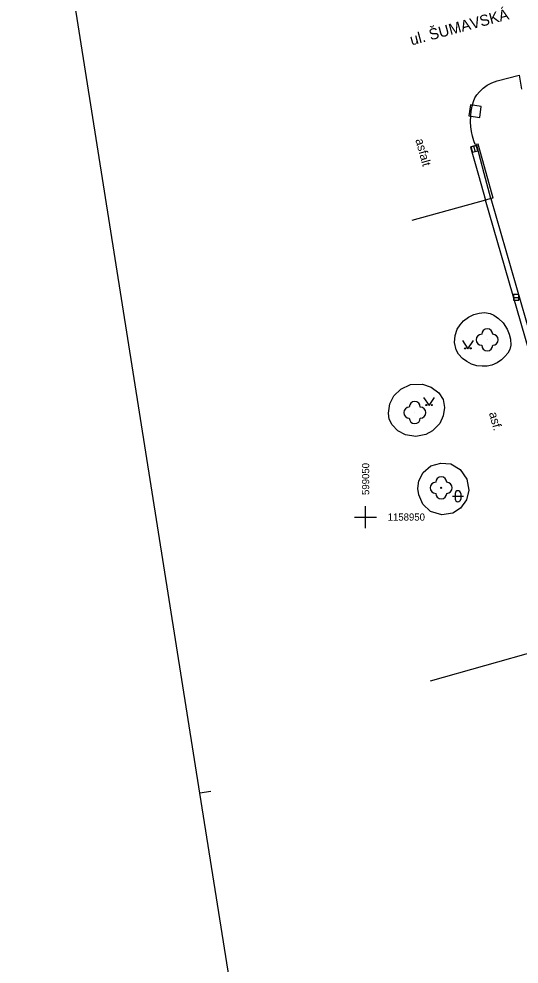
# Model space of a CAD drawing. Extents: x -599098 to -598820, y -1159597 to -1158744.
# Drawn here: x -599081.5 to -599036.1, y -1158990.5 to -1158904.8 of the extents above; entities that cross this region are included whole.
import ezdxf

# ---------------------------------------------------------------- set-up
doc = ezdxf.new("R2010")
doc.units = 0
for name, color, linetype in [('budovy', 7, 'Continuous'), ('druh pozemku stromy', 7, 'Continuous'), ('hektometrická síť', 7, 'Continuous'), ('kresba', 7, 'Continuous'), ('mapový rám legenda', 7, 'Continuous'), ('popisy', 7, 'Continuous'), ('značky IS', 7, 'Continuous')]:
    doc.layers.add(name, color=color, linetype=linetype)

msp = doc.modelspace()

# ---------------------------------------------------------------- linework, layer by layer
at = {"layer": 'budovy'}
msp.add_lwpolyline([(-599044.099, -1158964.859), (-599029.33, -1158960.69)], dxfattribs=at)
at = {"layer": 'druh pozemku stromy'}
for p, q in [((-599042.126, -1158948.116), (-599041.126, -1158948.116)), ((-599041.876, -1158947.866), (-599041.876, -1158948.366)), ((-599041.376, -1158947.866), (-599041.376, -1158948.366))]:
    msp.add_line(p, q, dxfattribs=at)
for points in [[(-599041.22, -1158934.01), (-599040.72, -1158934.76), (-599040.22, -1158934.01)], [(-599044.74, -1158939.15), (-599044.24, -1158939.9), (-599043.74, -1158939.15)]]:
    msp.add_lwpolyline(points, dxfattribs=at)
for centre, radius in [((-599038.97, -1158933.93), 0.0005), ((-599040.97, -1158934.71), 0.05), ((-599040.47, -1158934.71), 0.05), ((-599044.49, -1158939.85), 0.05), ((-599043.99, -1158939.85), 0.05), ((-599045.54, -1158940.53), 0.0005), ((-599043.14, -1158947.35), 0.05)]:
    msp.add_circle(centre, radius, dxfattribs=at)
for centre, radius, start, end in [((-599038.97, -1158933.43), 0.5, 0, 179.99999), ((-599039.47, -1158933.93), 0.5, 89.99999, 269.99999), ((-599038.47, -1158933.93), 0.5, 270, 89.99999), ((-599038.97, -1158934.43), 0.5, 179.99999, 359.99999), ((-599046.04, -1158940.53), 0.5, 89.99999, 269.99999), ((-599045.54, -1158940.03), 0.5, 0, 179.99999), ((-599045.04, -1158940.53), 0.5, 270, 89.99999), ((-599045.54, -1158941.03), 0.5, 179.99999, 359.99999), ((-599043.64, -1158947.35), 0.5, 90, 270), ((-599043.14, -1158946.85), 0.5, 0, 180), ((-599042.64, -1158947.35), 0.5, 270, 90), ((-599041.626, -1158947.866), 0.25, 0, 180), ((-599043.14, -1158947.85), 0.5, 180, 0), ((-599041.626, -1158948.366), 0.25, 180, 0)]:
    msp.add_arc(centre, radius, start, end, dxfattribs=at)
at = {"layer": 'hektometrická síť'}
for p, q in [((-599050, -1158951), (-599050, -1158949)), ((-599051, -1158950), (-599049, -1158950))]:
    msp.add_line(p, q, dxfattribs=at)
at = {"layer": 'kresba'}
for p, q in [((-599038.05, -1158910.45), (-599036.074, -1158909.955)), ((-599036.074, -1158909.955), (-599035.86, -1158911.22)), ((-599039.35, -1158911.13), (-599038.97, -1158910.86)), ((-599038.97, -1158910.86), (-599038.55, -1158910.63)), ((-599038.55, -1158910.63), (-599038.05, -1158910.45)), ((-599040.08, -1158912), (-599039.9, -1158911.72)), ((-599039.9, -1158911.72), (-599039.67, -1158911.44)), ((-599039.67, -1158911.44), (-599039.35, -1158911.13)), ((-599040.33, -1158912.76), (-599040.2, -1158912.34)), ((-599040.2, -1158912.34), (-599040.08, -1158912)), ((-599040.46, -1158913.61), (-599040.42, -1158913.21)), ((-599040.42, -1158913.21), (-599040.33, -1158912.76)), ((-599040.47, -1158914.17), (-599040.46, -1158913.61)), ((-599040.44, -1158914.63), (-599040.47, -1158914.17)), ((-599040.39, -1158915.05), (-599040.44, -1158914.63)), ((-599040.3, -1158915.48), (-599040.39, -1158915.05)), ((-599040.17, -1158915.91), (-599040.3, -1158915.48)), ((-599040.05, -1158916.24), (-599040.17, -1158915.91)), ((-599039.92, -1158916.31), (-599040.47, -1158916.46)), ((-599040.47, -1158916.46), (-599039.752, -1158918.994)), ((-599039.78, -1158916.2), (-599040.05, -1158916.24)), ((-599039.24, -1158918.849), (-599039.92, -1158916.31)), ((-599039.061, -1158918.799), (-599039.78, -1158916.2)), ((-599039.752, -1158918.994), (-599039.11, -1158921.26)), ((-599038.63, -1158921.13), (-599039.24, -1158918.849)), ((-599038.43, -1158921.08), (-599039.061, -1158918.799)), ((-599038.63, -1158921.13), (-599039.11, -1158921.26)), ((-599038.43, -1158921.08), (-599038.63, -1158921.13)), ((-599038.63, -1158921.13), (-599030.181, -1158950.522)), ((-599039.11, -1158921.26), (-599045.812, -1158923.116)), ((-599030.662, -1158950.66), (-599039.11, -1158921.26)), ((-599040.19, -1158931.63), (-599039.71, -1158931.51)), ((-599039.71, -1158931.51), (-599039.2, -1158931.47)), ((-599039.2, -1158931.47), (-599038.71, -1158931.54)), ((-599041.42, -1158932.57), (-599041.13, -1158932.22)), ((-599041.13, -1158932.22), (-599040.68, -1158931.88)), ((-599040.68, -1158931.88), (-599040.19, -1158931.63)), ((-599038.71, -1158931.54), (-599038.36, -1158931.71)), ((-599038.36, -1158931.71), (-599037.94, -1158932.01)), ((-599037.94, -1158932.01), (-599037.51, -1158932.39)), ((-599041.87, -1158933.54), (-599041.69, -1158932.97)), ((-599041.69, -1158932.97), (-599041.42, -1158932.57)), ((-599037.51, -1158932.39), (-599037.16, -1158932.98)), ((-599037.16, -1158932.98), (-599036.98, -1158933.41)), ((-599041.93, -1158934.18), (-599041.87, -1158933.54)), ((-599036.98, -1158933.41), (-599036.86, -1158933.87)), ((-599036.86, -1158933.87), (-599036.84, -1158934.42)), ((-599041.79, -1158934.85), (-599041.93, -1158934.18)), ((-599041.56, -1158935.23), (-599041.79, -1158934.85)), ((-599036.92, -1158934.82), (-599037.1, -1158935.15)), ((-599036.84, -1158934.42), (-599036.92, -1158934.82)), ((-599041.21, -1158935.63), (-599041.56, -1158935.23)), ((-599040.81, -1158935.89), (-599041.21, -1158935.63)), ((-599037.68, -1158935.76), (-599038.05, -1158936.02)), ((-599037.37, -1158935.46), (-599037.68, -1158935.76)), ((-599037.1, -1158935.15), (-599037.37, -1158935.46)), ((-599040.39, -1158936.13), (-599040.81, -1158935.89)), ((-599039.92, -1158936.28), (-599040.39, -1158936.13)), ((-599039.43, -1158936.32), (-599039.92, -1158936.28)), ((-599038.98, -1158936.31), (-599039.43, -1158936.32)), ((-599038.56, -1158936.22), (-599038.98, -1158936.31)), ((-599038.05, -1158936.02), (-599038.56, -1158936.22)), ((-599046.8, -1158938.41), (-599045.94, -1158937.99)), ((-599045.94, -1158937.99), (-599044.85, -1158937.95)), ((-599044.85, -1158937.95), (-599044.04, -1158938.22)), ((-599044.04, -1158938.22), (-599043.37, -1158938.74)), ((-599047.81, -1158939.74), (-599047.43, -1158939.02)), ((-599047.43, -1158939.02), (-599046.8, -1158938.41)), ((-599043.37, -1158938.74), (-599042.95, -1158939.35)), ((-599047.93, -1158940.59), (-599047.81, -1158939.74)), ((-599042.85, -1158940.06), (-599042.97, -1158940.83)), ((-599042.95, -1158939.35), (-599042.85, -1158940.06)), ((-599047.85, -1158941.13), (-599047.93, -1158940.59)), ((-599042.97, -1158940.83), (-599043.26, -1158941.51)), ((-599047.59, -1158941.65), (-599047.85, -1158941.13)), ((-599047.09, -1158942.17), (-599047.59, -1158941.65)), ((-599043.26, -1158941.51), (-599043.92, -1158942.18)), ((-599046.39, -1158942.56), (-599047.09, -1158942.17)), ((-599045.44, -1158942.71), (-599046.39, -1158942.56)), ((-599044.55, -1158942.53), (-599045.44, -1158942.71)), ((-599043.92, -1158942.18), (-599044.55, -1158942.53))]:
    msp.add_line(p, q, dxfattribs=at)
msp.add_lwpolyline([(-599045.25, -1158947.42), (-599045.17, -1158946.71), (-599044.79, -1158945.95), (-599044.07, -1158945.35), (-599043.18, -1158945.1), (-599042.26, -1158945.19), (-599041.42, -1158945.68), (-599040.83, -1158946.58), (-599040.63, -1158947.55), (-599040.84, -1158948.45), (-599041.39, -1158949.19), (-599042.1, -1158949.65), (-599043.1, -1158949.81), (-599044.12, -1158949.5), (-599044.81, -1158948.82), (-599045.18, -1158948), (-599045.25, -1158947.42)], dxfattribs=at)
at = {"layer": 'mapový rám legenda'}
for p, q in [((-599065.032, -1158975.034), (-599081.457, -1158871.327)), ((-599064.044, -1158974.877), (-599065.032, -1158975.034)), ((-599048.606, -1159078.741), (-599065.032, -1158975.034))]:
    msp.add_line(p, q, dxfattribs=at)
at = {"layer": 'značky IS'}
for p, q in [((-599040.492, -1158912.643), (-599040.637, -1158913.632)), ((-599039.503, -1158912.788), (-599040.492, -1158912.643)), ((-599039.648, -1158913.777), (-599039.503, -1158912.788)), ((-599040.637, -1158913.632), (-599039.648, -1158913.777)), ((-599040.208, -1158916.379), (-599040.072, -1158916.861)), ((-599036.59, -1158930.09), (-599036.09, -1158930.09))]:
    msp.add_line(p, q, dxfattribs=at)
for points in [[(-599040.45, -1158916.448), (-599040.313, -1158916.929), (-599039.831, -1158916.792), (-599039.968, -1158916.311)], [(-599036.59, -1158930.34), (-599036.09, -1158930.34), (-599036.09, -1158929.84), (-599036.59, -1158929.84)]]:
    msp.add_lwpolyline(points, close=True, dxfattribs=at)

# ---------------------------------------------------------------- texts
at = {"layer": 'hektometrická síť'}
msp.add_text('599050', height=0.65, rotation=90, dxfattribs=at).set_placement((-599049.675, -1158948))
msp.add_text('1158950', height=0.65, dxfattribs=at).set_placement((-599048, -1158950.325))
at = {"layer": 'popisy'}
for s, height, rotation, p in [('ul. ŠUMAVSKÁ', 1, 15.01376, (-599045.829, -1158907.251)), ('asfalt', 0.8, 285.56013, (-599045.495, -1158915.806)), ('asf.', 0.8, 285.35656, (-599038.817, -1158940.584))]:
    msp.add_text(s, height=height, rotation=rotation, dxfattribs=at).set_placement(p)

doc.saveas('drawing.dxf')
